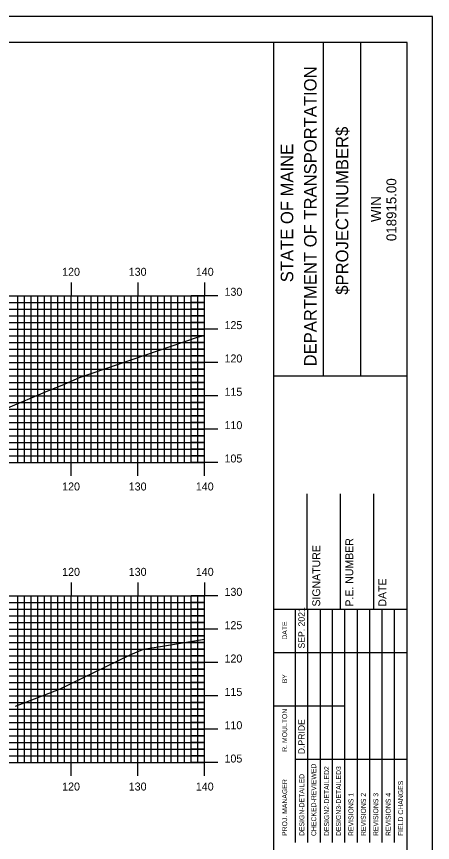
# Model space of a CAD drawing. Extents: x 1685979 to 1686323, y 461260 to 461480.
# Drawn here: x 1686257.1 to 1686319.5, y 461356.1 to 461480 of the extents above; entities that cross this region are included whole.
import ezdxf

# ---------------------------------------------------------------- set-up
doc = ezdxf.new("R2010")
doc.units = 0
for name, color, linetype in [('BORDER', 7, 'Continuous'), ('H_V ANNOTATION', 7, 'Continuous'), ('MAJOR', 7, 'Continuous'), ('MINOR', 7, 'Continuous'), ('PLOT BOUNDARY', 7, 'Continuous'), ('S_Roadway_Centerline', 7, 'Continuous')]:
    doc.layers.add(name, color=color, linetype=linetype)

msp = doc.modelspace()

# ---------------------------------------------------------------- linework, layer by layer
at = {"layer": 'BORDER'}
for p, q in [((1686295.66, 461266.07), (1686295.66, 461476.07)), ((1686303.11, 461426.07), (1686303.11, 461476.07)), ((1686308.7, 461426.07), (1686308.7, 461476.07)), ((1686295.66, 461426.06), (1686315.66, 461426.06)), ((1686300.66, 461391.08), (1686300.66, 461408.37)), ((1686305.66, 461391.08), (1686305.66, 461408.37)), ((1686310.66, 461391.08), (1686310.66, 461408.37)), ((1686295.66, 461391.08), (1686315.66, 461391.08))]:
    msp.add_line(p, q, dxfattribs=at)
msp.add_lwpolyline([(1685995.66, 461266.07), (1686315.66, 461266.07), (1686315.66, 461476.07), (1685995.66, 461476.07)], close=True, dxfattribs=at)
for points in [[(1686298.89, 461384.58), (1686298.89, 461391.08)], [(1686300.75, 461356.08), (1686300.75, 461391.08)], [(1686302.61, 461391.08), (1686302.61, 461356.08)], [(1686304.48, 461356.08), (1686304.48, 461391.08)], [(1686306.34, 461356.08), (1686306.34, 461391.08)], [(1686308.2, 461356.08), (1686308.2, 461391.08)], [(1686310.07, 461356.08), (1686310.07, 461391.08)], [(1686311.93, 461356.08), (1686311.93, 461391.08)], [(1686313.79, 461356.08), (1686313.79, 461391.08)], [(1686298.89, 461356.08), (1686298.89, 461389.67)], [(1686295.66, 461384.58), (1686315.66, 461384.58)], [(1686295.66, 461376.58), (1686298.89, 461376.58)], [(1686298.89, 461376.58), (1686306.34, 461376.58)], [(1686298.89, 461368.58), (1686315.66, 461368.58)]]:
    msp.add_lwpolyline(points, dxfattribs=at)
at = {"layer": 'MAJOR'}
for p, q in [((1686265.26, 461440.08), (1686265.26, 461438.07)), ((1686275.26, 461440.08), (1686275.26, 461438.07)), ((1686285.26, 461440.08), (1686285.26, 461438.07)), ((1686005.26, 461438.07), (1686285.26, 461438.07)), ((1686005.26, 461438.07), (1686285.26, 461438.07)), ((1686265.26, 461413.07), (1686265.26, 461438.07)), ((1686275.26, 461413.07), (1686275.26, 461438.07)), ((1686287.26, 461438.07), (1686283.25, 461438.07)), ((1686285.26, 461413.07), (1686285.26, 461438.07)), ((1686285.26, 461413.07), (1686285.26, 461438.07)), ((1686005.26, 461433.07), (1686285.26, 461433.07)), ((1686287.26, 461433.07), (1686283.25, 461433.07)), ((1686005.26, 461428.07), (1686285.26, 461428.07)), ((1686287.26, 461428.07), (1686283.25, 461428.07)), ((1686005.26, 461423.07), (1686285.26, 461423.07)), ((1686287.26, 461423.07), (1686283.25, 461423.07)), ((1686005.26, 461418.07), (1686285.26, 461418.07)), ((1686287.26, 461418.07), (1686283.25, 461418.07)), ((1686005.26, 461413.07), (1686285.26, 461413.07)), ((1686005.26, 461413.07), (1686285.26, 461413.07)), ((1686265.26, 461411.07), (1686265.26, 461413.07)), ((1686275.26, 461411.07), (1686275.26, 461413.07)), ((1686287.26, 461413.07), (1686283.25, 461413.07)), ((1686285.26, 461411.07), (1686285.26, 461413.07)), ((1686265.26, 461395.08), (1686265.26, 461393.07)), ((1686275.26, 461395.08), (1686275.26, 461393.07)), ((1686285.26, 461395.08), (1686285.26, 461393.07)), ((1686005.26, 461393.07), (1686285.26, 461393.07)), ((1686005.26, 461393.07), (1686285.26, 461393.07)), ((1686265.26, 461368.07), (1686265.26, 461393.07)), ((1686275.26, 461368.07), (1686275.26, 461393.07)), ((1686287.26, 461393.07), (1686283.25, 461393.07)), ((1686285.26, 461368.07), (1686285.26, 461393.07)), ((1686285.26, 461368.07), (1686285.26, 461393.07)), ((1686005.26, 461388.07), (1686285.26, 461388.07)), ((1686287.26, 461388.07), (1686283.25, 461388.07)), ((1686005.26, 461383.07), (1686285.26, 461383.07)), ((1686287.26, 461383.07), (1686283.25, 461383.07)), ((1686005.26, 461378.07), (1686285.26, 461378.07)), ((1686287.26, 461378.07), (1686283.25, 461378.07)), ((1686005.26, 461373.07), (1686285.26, 461373.07)), ((1686287.26, 461373.07), (1686283.25, 461373.07)), ((1686005.26, 461368.07), (1686285.26, 461368.07)), ((1686005.26, 461368.07), (1686285.26, 461368.07)), ((1686265.26, 461366.07), (1686265.26, 461368.07)), ((1686275.26, 461366.07), (1686275.26, 461368.07)), ((1686287.26, 461368.07), (1686283.25, 461368.07)), ((1686285.26, 461366.07), (1686285.26, 461368.07))]:
    msp.add_line(p, q, dxfattribs=at)
at = {"layer": 'MINOR'}
for p, q in [((1686257.26, 461413.07), (1686257.26, 461438.07)), ((1686258.26, 461413.07), (1686258.26, 461438.07)), ((1686259.26, 461413.07), (1686259.26, 461438.07)), ((1686260.26, 461413.07), (1686260.26, 461438.07)), ((1686261.26, 461413.07), (1686261.26, 461438.07)), ((1686262.26, 461413.07), (1686262.26, 461438.07)), ((1686263.26, 461413.07), (1686263.26, 461438.07)), ((1686264.26, 461413.07), (1686264.26, 461438.07)), ((1686266.26, 461413.07), (1686266.26, 461438.07)), ((1686267.26, 461413.07), (1686267.26, 461438.07)), ((1686268.26, 461413.07), (1686268.26, 461438.07)), ((1686269.26, 461413.07), (1686269.26, 461438.07)), ((1686270.26, 461413.07), (1686270.26, 461438.07)), ((1686271.26, 461413.07), (1686271.26, 461438.07)), ((1686272.26, 461413.07), (1686272.26, 461438.07)), ((1686273.26, 461413.07), (1686273.26, 461438.07)), ((1686274.26, 461413.07), (1686274.26, 461438.07)), ((1686276.26, 461413.07), (1686276.26, 461438.07)), ((1686277.26, 461413.07), (1686277.26, 461438.07)), ((1686278.26, 461413.07), (1686278.26, 461438.07)), ((1686279.26, 461413.07), (1686279.26, 461438.07)), ((1686280.26, 461413.07), (1686280.26, 461438.07)), ((1686281.26, 461413.07), (1686281.26, 461438.07)), ((1686282.26, 461413.07), (1686282.26, 461438.07)), ((1686283.26, 461413.07), (1686283.26, 461438.07)), ((1686284.26, 461413.07), (1686284.26, 461438.07)), ((1686005.26, 461437.07), (1686285.26, 461437.07)), ((1686285.26, 461437.07), (1686283.25, 461437.07)), ((1686005.26, 461436.07), (1686285.26, 461436.07)), ((1686005.26, 461435.07), (1686285.26, 461435.07)), ((1686285.26, 461436.07), (1686283.25, 461436.07)), ((1686285.26, 461435.07), (1686283.25, 461435.07)), ((1686005.26, 461434.07), (1686285.26, 461434.07)), ((1686285.26, 461434.07), (1686283.25, 461434.07)), ((1686005.26, 461432.07), (1686285.26, 461432.07)), ((1686285.26, 461432.07), (1686283.25, 461432.07)), ((1686005.26, 461431.07), (1686285.26, 461431.07)), ((1686005.26, 461430.07), (1686285.26, 461430.07)), ((1686285.26, 461431.07), (1686283.25, 461431.07)), ((1686285.26, 461430.07), (1686283.25, 461430.07)), ((1686005.26, 461429.07), (1686285.26, 461429.07)), ((1686285.26, 461429.07), (1686283.25, 461429.07)), ((1686005.26, 461427.07), (1686285.26, 461427.07)), ((1686285.26, 461427.07), (1686283.25, 461427.07)), ((1686005.26, 461426.07), (1686285.26, 461426.07)), ((1686005.26, 461425.07), (1686285.26, 461425.07)), ((1686285.26, 461426.07), (1686283.25, 461426.07)), ((1686285.26, 461425.07), (1686283.25, 461425.07)), ((1686005.26, 461424.07), (1686285.26, 461424.07)), ((1686285.26, 461424.07), (1686283.25, 461424.07)), ((1686005.26, 461422.07), (1686285.26, 461422.07)), ((1686285.26, 461422.07), (1686283.25, 461422.07)), ((1686005.26, 461421.07), (1686285.26, 461421.07)), ((1686005.26, 461420.07), (1686285.26, 461420.07)), ((1686285.26, 461421.07), (1686283.25, 461421.07)), ((1686285.26, 461420.07), (1686283.25, 461420.07)), ((1686005.26, 461419.07), (1686285.26, 461419.07)), ((1686285.26, 461419.07), (1686283.25, 461419.07)), ((1686005.26, 461417.07), (1686285.26, 461417.07)), ((1686285.26, 461417.07), (1686283.25, 461417.07)), ((1686005.26, 461416.07), (1686285.26, 461416.07)), ((1686285.26, 461416.07), (1686283.25, 461416.07)), ((1686005.26, 461415.07), (1686285.26, 461415.07)), ((1686005.26, 461414.07), (1686285.26, 461414.07)), ((1686285.26, 461415.07), (1686283.25, 461415.07)), ((1686285.26, 461414.07), (1686283.25, 461414.07)), ((1686257.26, 461368.07), (1686257.26, 461393.07)), ((1686258.26, 461368.07), (1686258.26, 461393.07)), ((1686259.26, 461368.07), (1686259.26, 461393.07)), ((1686260.26, 461368.07), (1686260.26, 461393.07)), ((1686261.26, 461368.07), (1686261.26, 461393.07)), ((1686262.26, 461368.07), (1686262.26, 461393.07)), ((1686263.26, 461368.07), (1686263.26, 461393.07)), ((1686264.26, 461368.07), (1686264.26, 461393.07)), ((1686266.26, 461368.07), (1686266.26, 461393.07)), ((1686267.26, 461368.07), (1686267.26, 461393.07)), ((1686268.26, 461368.07), (1686268.26, 461393.07)), ((1686269.26, 461368.07), (1686269.26, 461393.07)), ((1686270.26, 461368.07), (1686270.26, 461393.07)), ((1686271.26, 461368.07), (1686271.26, 461393.07)), ((1686272.26, 461368.07), (1686272.26, 461393.07)), ((1686273.26, 461368.07), (1686273.26, 461393.07)), ((1686274.26, 461368.07), (1686274.26, 461393.07)), ((1686276.26, 461368.07), (1686276.26, 461393.07)), ((1686277.26, 461368.07), (1686277.26, 461393.07)), ((1686278.26, 461368.07), (1686278.26, 461393.07)), ((1686279.26, 461368.07), (1686279.26, 461393.07)), ((1686280.26, 461368.07), (1686280.26, 461393.07)), ((1686281.26, 461368.07), (1686281.26, 461393.07)), ((1686282.26, 461368.07), (1686282.26, 461393.07)), ((1686283.26, 461368.07), (1686283.26, 461393.07)), ((1686284.26, 461368.07), (1686284.26, 461393.07)), ((1686005.26, 461392.07), (1686285.26, 461392.07)), ((1686285.26, 461392.07), (1686283.25, 461392.07)), ((1686005.26, 461391.07), (1686285.26, 461391.07)), ((1686285.26, 461391.07), (1686283.25, 461391.07)), ((1686005.26, 461390.07), (1686285.26, 461390.07)), ((1686005.26, 461389.07), (1686285.26, 461389.07)), ((1686285.26, 461390.07), (1686283.25, 461390.07)), ((1686285.26, 461389.07), (1686283.25, 461389.07)), ((1686005.26, 461387.07), (1686285.26, 461387.07)), ((1686285.26, 461387.07), (1686283.25, 461387.07)), ((1686005.26, 461386.07), (1686285.26, 461386.07)), ((1686285.26, 461386.07), (1686283.25, 461386.07)), ((1686005.26, 461385.07), (1686285.26, 461385.07)), ((1686285.26, 461385.07), (1686283.25, 461385.07)), ((1686005.26, 461384.07), (1686285.26, 461384.07)), ((1686285.26, 461384.07), (1686283.25, 461384.07)), ((1686005.26, 461382.07), (1686285.26, 461382.07)), ((1686285.26, 461382.07), (1686283.25, 461382.07)), ((1686005.26, 461381.07), (1686285.26, 461381.07)), ((1686285.26, 461381.07), (1686283.25, 461381.07)), ((1686005.26, 461380.07), (1686285.26, 461380.07)), ((1686285.26, 461380.07), (1686283.25, 461380.07)), ((1686005.26, 461379.07), (1686285.26, 461379.07)), ((1686285.26, 461379.07), (1686283.25, 461379.07)), ((1686005.26, 461377.07), (1686285.26, 461377.07)), ((1686285.26, 461377.07), (1686283.25, 461377.07)), ((1686005.26, 461376.07), (1686285.26, 461376.07)), ((1686285.26, 461376.07), (1686283.25, 461376.07)), ((1686005.26, 461375.07), (1686285.26, 461375.07)), ((1686285.26, 461375.07), (1686283.25, 461375.07)), ((1686005.26, 461374.07), (1686285.26, 461374.07)), ((1686285.26, 461374.07), (1686283.25, 461374.07)), ((1686005.26, 461372.07), (1686285.26, 461372.07)), ((1686285.26, 461372.07), (1686283.25, 461372.07)), ((1686005.26, 461371.07), (1686285.26, 461371.07)), ((1686285.26, 461371.07), (1686283.25, 461371.07)), ((1686005.26, 461370.07), (1686285.26, 461370.07)), ((1686285.26, 461370.07), (1686283.25, 461370.07)), ((1686005.26, 461369.07), (1686285.26, 461369.07)), ((1686285.26, 461369.07), (1686283.25, 461369.07))]:
    msp.add_line(p, q, dxfattribs=at)
at = {"layer": 'PLOT BOUNDARY'}
msp.add_lwpolyline([(1685979.47, 461259.95), (1686319.47, 461259.95), (1686319.47, 461479.95), (1685979.47, 461479.95)], close=True, dxfattribs=at)
at = {"layer": 'S_Roadway_Centerline'}
for points in [[(1686254.82, 461420.85), (1686262.37, 461424.06), (1686263.88, 461424.68), (1686266.53, 461425.84), (1686284.35, 461431.92), (1686285.26, 461432.11)], [(1686256.89, 461376.53), (1686263.48, 461379.09), (1686274.1, 461384.23), (1686276.1, 461385.09), (1686278.96, 461385.5), (1686285.26, 461386.59)]]:
    msp.add_lwpolyline(points, dxfattribs=at)

# ---------------------------------------------------------------- texts
at = {"layer": 'BORDER'}
for s, height, p in [('DEPARTMENT OF TRANSPORTATION', 1.8635, (1686302.07, 461427.48)), ('$PROJECTNUMBER$', 1.8635, (1686306.84, 461438.23)), ('STATE OF MAINE', 1.8635, (1686298.57, 461440.1)), ('018915.00', 1.491, (1686314.05, 461446.27)), ('WIN', 1.491, (1686311.73, 461449.13)), ('P.E. NUMBER', 1.1811, (1686307.58, 461391.46)), ('SIGNATURE', 1.181, (1686302.62, 461391.46)), ('DATE', 1.181, (1686312.54, 461391.46)), ('SEP. 2021', 0.969, (1686300.3, 461385.17)), ('DATE', 0.743, (1686297.66, 461386.49)), ('BY', 0.743, (1686297.66, 461379.95)), ('R. MOULTON', 0.745, (1686297.66, 461369.68)), ('D.PRIDE', 0.969, (1686300.3, 461369.32)), ('CHECKED-REVIEWED', 0.7455, (1686302.02, 461357.05)), ('DESIGN2-DETAILED2', 0.7455, (1686303.96, 461357.05)), ('DESIGN3-DETAILED3', 0.7455, (1686305.74, 461357.05)), ('DESIGN-DETAILED', 0.7455, (1686300.23, 461357.05)), ('PROJ. MANAGER', 0.7455, (1686297.66, 461357.05)), ('FIELD CHANGES', 0.7455, (1686315.06, 461357.05)), ('REVISIONS 1', 0.7455, (1686307.61, 461357.05)), ('REVISIONS 2', 0.7455, (1686309.47, 461357.05)), ('REVISIONS 3', 0.7455, (1686311.33, 461357.05)), ('REVISIONS 4', 0.7455, (1686313.2, 461357.05))]:
    msp.add_text(s, height=height, rotation=90, dxfattribs=at).set_placement(p)
at = {"layer": 'H_V ANNOTATION'}
for s, p in [('120', (1686263.9, 461441.07)), ('130', (1686273.89, 461441.07)), ('140', (1686283.96, 461441.07)), ('130', (1686288.26, 461438.07)), ('125', (1686288.26, 461433.07)), ('120', (1686288.26, 461428.07)), ('115', (1686288.26, 461423.07)), ('110', (1686288.26, 461418.07)), ('105', (1686288.26, 461413.07)), ('120', (1686263.9, 461408.87)), ('130', (1686273.89, 461408.87)), ('140', (1686283.96, 461408.87)), ('120', (1686263.9, 461396.07)), ('130', (1686273.89, 461396.07)), ('140', (1686283.96, 461396.07)), ('130', (1686288.26, 461393.07)), ('125', (1686288.26, 461388.07)), ('120', (1686288.26, 461383.07)), ('115', (1686288.26, 461378.07)), ('110', (1686288.26, 461373.07)), ('105', (1686288.26, 461368.07)), ('120', (1686263.9, 461363.87)), ('130', (1686273.89, 461363.87)), ('140', (1686283.96, 461363.87))]:
    msp.add_text(s, height=1.2, dxfattribs=at).set_placement(p)

doc.saveas('drawing.dxf')
